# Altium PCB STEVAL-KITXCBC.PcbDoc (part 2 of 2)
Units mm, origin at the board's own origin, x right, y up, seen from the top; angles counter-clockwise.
Board outline 110 x 100 mm, 4 copper layers (Top Layer, Ground Layer, Power Layer, Bottom Layer), stack 1.572 mm thick; 141 components, 96 nets, 501 pads, 315 vias.
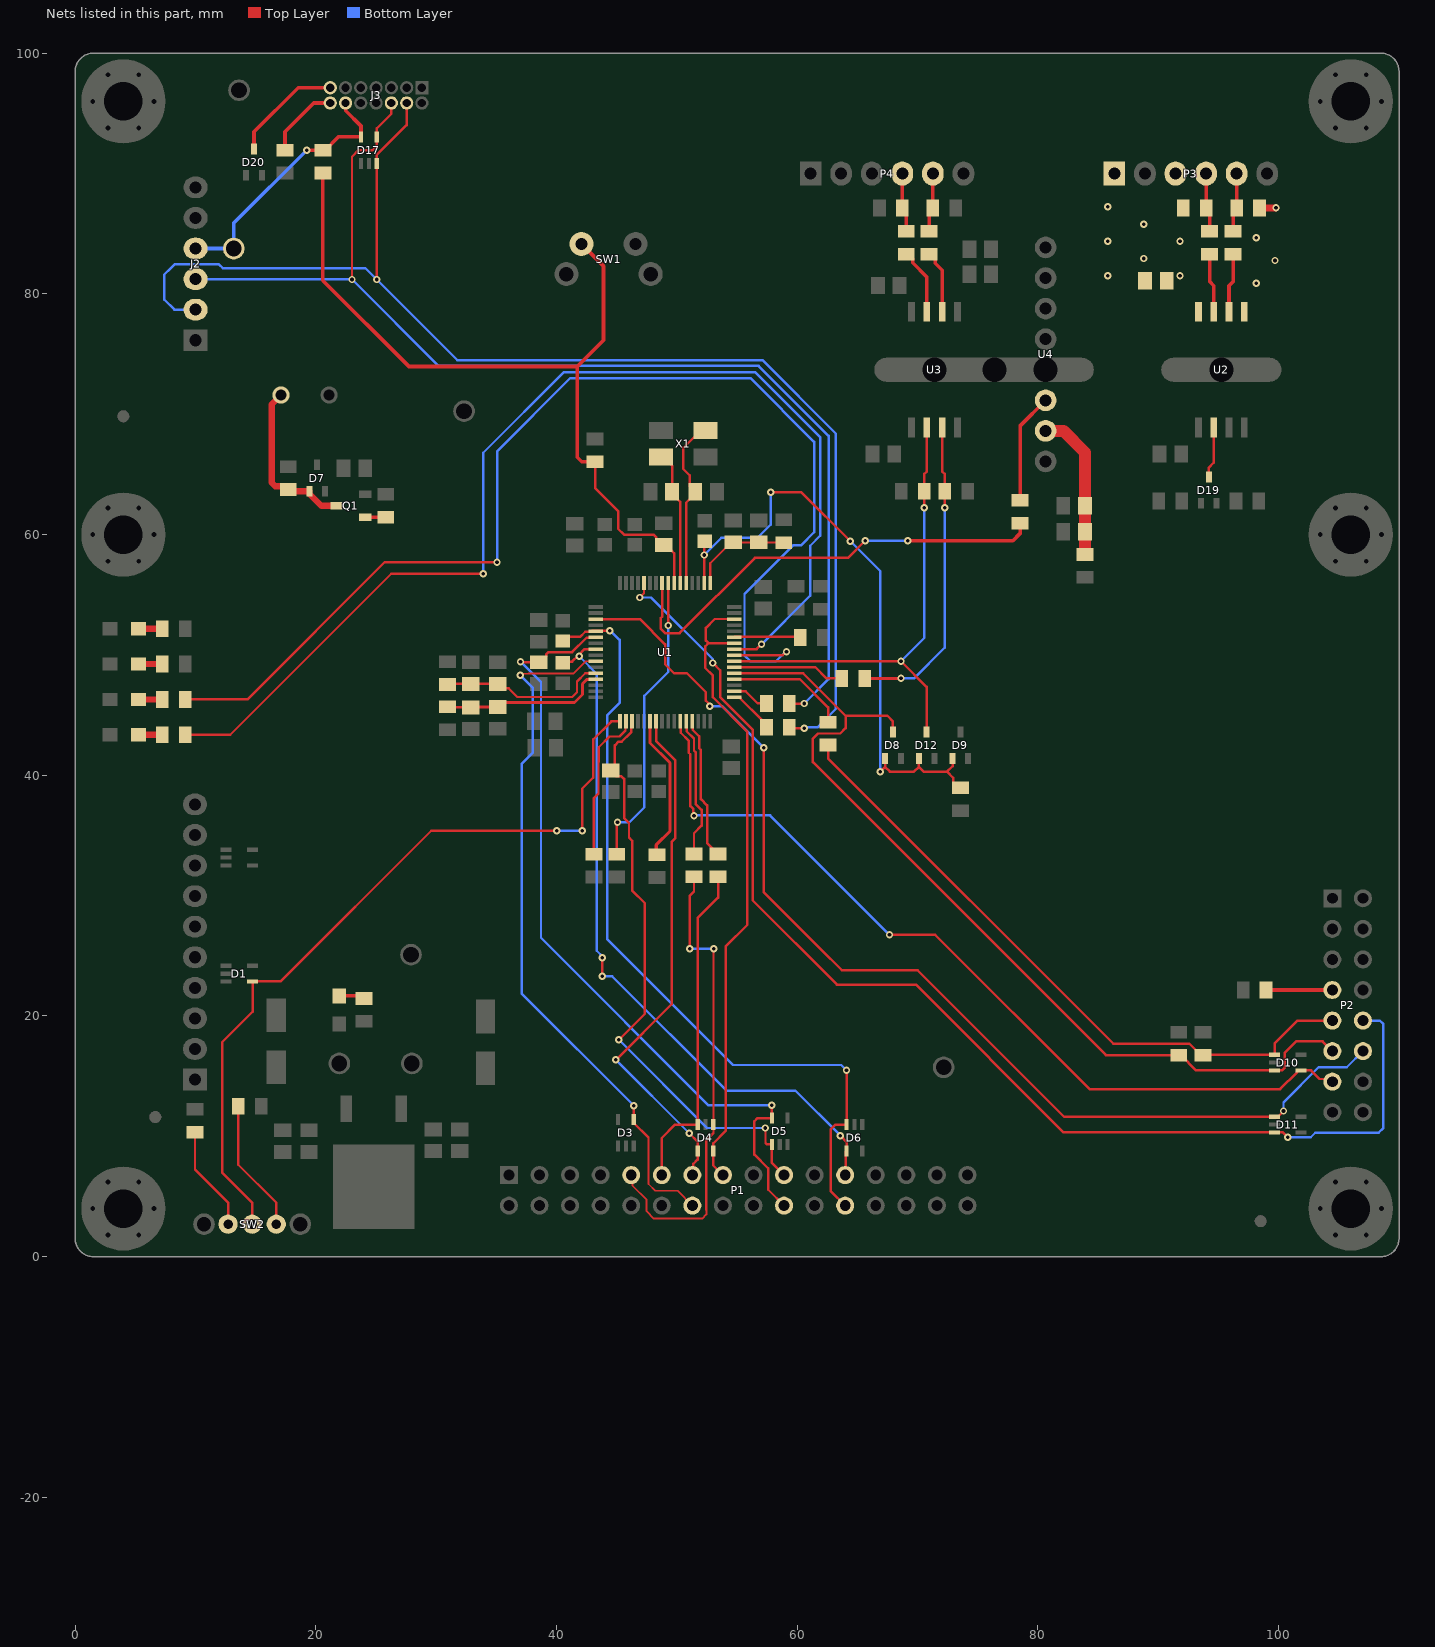
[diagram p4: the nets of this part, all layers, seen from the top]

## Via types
v1: diameter 0.61, hole 0.305, Top Layer to Bottom Layer, tented both sides, 249 vias
v2: diameter 0.6, hole 0.3, Top Layer to Bottom Layer, tented both sides, 45 vias
v3: diameter 0.65, hole 0.3, Top Layer to Bottom Layer, 12 vias
v4: diameter 0.62, hole 0.31, Top Layer to Bottom Layer, 9 vias

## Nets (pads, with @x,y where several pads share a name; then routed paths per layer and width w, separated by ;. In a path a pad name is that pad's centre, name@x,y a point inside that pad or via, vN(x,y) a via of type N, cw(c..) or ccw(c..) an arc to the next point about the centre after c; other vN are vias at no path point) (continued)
Led2: R36.2 U1.56 | length 100
  Top Layer w0.203: R36.2@9.009,46.306 14.319,46.306 25.713,57.7 v1(35.05,57.7) ; U1.56@54.764,49.979 58.786,49.979 59.061,50.254 v1(59.109,50.254)
  Bottom Layer w0.203: v1(35.05,57.7) 35.05,66.916 41.134,73 56.1,73 61.4,67.7 61.4,60.2 60.3,59.1 59.652,59.1 55.615,55.063 55.615,49.967 56.103,49.479 58.228,49.479 59.003,50.254 v1(59.109,50.254)
Led3: R37.2 U1.57 | length 95.2
  Top Layer w0.203: R37.2@9.009,43.369 12.884,43.369 26.264,56.75 v1(33.9,56.75) ; U1.57@54.764,50.479 56.623,50.479 v1(57.026,50.882)
  Bottom Layer w0.203: v1(33.9,56.75) 33.9,66.8 40.6,73.5 56.5,73.5 61.9,68.1 61.9,59.9 61.072,59.072 61.072,54.928 v1(57.026,50.882)
LINEen: D3.4 P1.14 U1.26 | length 58.8
  Top Layer w0.152: v4(36.969,48.307) 37.106,48.444 37.663,48.444 37.688,48.469 41.429,48.469 42.439,49.479 U1.26@43.264,49.479 ; 47.636,8.339 47.636,6.036 48.2,5.472 50.048,5.472 P1.14@51.28,4.24
  Top Layer w0.203: v1(46.406,12.548) 46.406,11.121 47.636,9.891 47.636,8.339
  Bottom Layer w0.203: v4(36.969,48.307) v4@37.117,48.16 ; v4@37.117,48.307 v4@37.117,48.16 ; v1(46.406,12.548) 37.117,21.837 37.117,40.976 38.031,41.891 38.031,47.246 v4@37.117,48.16
NetBZ1_2: BZ1.2 D7.1 Q1.3 R16.1 | length 13.8
  Top Layer w0.508: BZ1.2@17.1,71.6 16.327,70.827 16.327,64.319 16.625,64.021 17.429,64.021 R16.1@17.7,63.75 ; R16.1@17.775,63.75 17.95,63.75 18.1,63.6 D7.1@19.45,63.6 19.45,63.408 20.458,62.4 Q1.3@21.7,62.4
NetC22_1: C22.1 C23.1 R28.2 U1.29 | length 13.8
  Top Layer w0.203: R28.2@30.933,45.697 30.968,45.662 C22.1@32.857,45.662
  Top Layer w0.254: C22.1@32.857,45.647 32.872,45.662 C23.1@35.107,45.662 35.32,45.662 35.705,46.047 41.49,46.047 42.151,46.708 42.151,47.604 42.505,47.958 43.243,47.958 U1.29@43.264,47.979
NetC25_1: C25.1 C26.1 R29.2 U1.1 | length 8.5
  Top Layer w0.203: U1.1@52.764,55.979 52.764,57.619 54.094,58.948 54.244,58.948 C26.1@54.666,59.371 54.691,59.346 56.808,59.346 58.853,59.346 R29.2@58.878,59.321
NetC28_1: C28.1 C29.1 R39.2 U1.28 | length 14.1
  Top Layer w0.203: R39.2@30.933,47.55 30.983,47.6 C28.1@32.857,47.6 C29.1@35.107,47.6 35.489,47.218 35.639,47.218 36.018,47.218 36.732,46.505 41.301,46.505 41.693,46.897 41.693,47.793 42.38,48.479 U1.28@43.264,48.479
NetC30_1: C30.1 C31.1 R41.1 U4.2 | length 12.5
  Top Layer w1: U4.2@80.642,68.62 82.118,68.62 83.9,66.838 C31.1@83.9,62.384 C30.1@83.9,60.234 R41.1@83.9,58.35
NetD18_1: D18.1 R45.1 | length 2.1
  Top Layer w0.3: D18.1@21.948,21.675 23.775,21.675 R45.1@24,21.45
NetD19_3: D19.3 U2.2 | length 4.3
  Top Layer w0.203: D19.3@94.2,64.8 94.2,65.573 94.605,65.978 U2.2@94.605,68.899
NetD20_3: D20.3 J3.13 | length 9.3
  Top Layer w0.3: D20.3@14.854,92.056 14.854,93.464 18.525,97.135 J3.13@21.19,97.135
NetJ3_14: J3.14 R44.1 | length 6.3
  Top Layer w0.3: R44.1@17.43,91.95 17.43,93.486 19.809,95.865 J3.14@21.19,95.865
NetLED0_1: LED0.1 R34.1 | length 2
  Top Layer w0.508: LED0.1@5.244,52.178 R34.1@7.236,52.178
NetLED1_1: LED1.1 R35.1 | length 1.9
  Top Layer w0.508: LED1.1@5.244,49.242 R35.1@7.109,49.242
NetLED2_1: LED2.1 R36.1 | length 1.9
  Top Layer w0.508: LED2.1@5.244,46.305 R36.1@7.109,46.305
NetLED3_1: LED3.1 R37.1 | length 1.9
  Top Layer w0.508: LED3.1@5.244,43.369 R37.1@7.109,43.369
NetP2_7: P2.7 R13.2 | length 5.5
  Top Layer w0.3: R13.2@98.95,22.16 P2.7@104.46,22.16
NetP3_4: P3.4 R23.1 R26.2 | length 4.9
  Top Layer w0.3: P3.4@93.97,90 R23.1@93.97,87.147 94.266,86.851 R26.2@94.266,85.204
NetP3_5: P3.5 R24.1 R27.2 | length 4.9
  Top Layer w0.3: R27.2@96.214,85.204 96.214,86.851 R24.1@96.51,87.147 P3.5@96.51,90
NetP4_4: P4.4 R32.1 R38.2 | length 4.9
  Top Layer w0.3: P4.4@68.73,90 R32.1@68.73,87.15 69.05,86.83 R38.2@69.05,85.2
NetP4_5: P4.5 R33.1 R40.2 | length 4.9
  Top Layer w0.3: R40.2@70.95,85.2 70.95,86.83 R33.1@71.27,87.15 P4.5@71.27,90
NetQ1_1: Q1.1 R20.1 | length 1.7
  Top Layer w0.3: Q1.1@24.1,61.45 R20.1@25.8,61.45
NetR3_1: R3.1 U1.8 | length 24.9
  Top Layer w0.203: R3.1@45,33.45 45,36.038 v1(45.06,36.097) ; U1.8@49.264,55.979 49.264,52.466 v1(49.279,52.451)
  Bottom Layer w0.203: v1(45.06,36.097) 46.046,36.097 47.298,37.349 47.298,46.608 49.279,48.589 v1(49.279,52.451)
NetR4_1: R4.1 U1.38 | length 12.3
  Top Layer w0.254: U1.38@47.764,44.479 47.764,42.689 49.42,41.033 49.42,35.359 48.28,34.219 48.28,33.469 R4.1@48.342,33.407
NetR5_1: R5.1 U1.44 | length 11.8
  Top Layer w0.203: U1.44@50.764,44.479 50.815,44.428 50.815,43.867 50.817,43.865 50.817,43.65 51.416,43.05 51.416,42.054 51.554,41.916 51.554,37.625 52.051,37.127 52.051,35.821 51.416,35.186 R5.1@51.416,33.457
NetR6_1: R6.1 U1.52 | length 10
  Top Layer w0.203: U1.52@54.764,47.979 60.216,47.979 62.557,45.638 R6.1@62.557,44.422
NetR7_1: R7.1 U1.45 | length 11.9
  Top Layer w0.203: U1.45@51.264,44.479 51.315,44.428 51.315,43.762 51.848,43.229 51.848,42.232 51.985,42.095 51.985,38.015 52.5,37.5 52.5,34.379 R7.1@53.421,33.457
NetR8_2: R8.2 U1.49 | length 3.9
  Top Layer w0.203: U1.49@54.764,46.479 55.209,46.479 55.259,46.428 55.259,46.391 57.021,44.63 57.021,44.332 R8.2@57.444,43.909
NetR9_1: R9.1 U1.54 | length 9.3
  Top Layer w0.203: U1.54@54.764,48.979 61.504,48.979 62.426,48.057 R9.1@63.703,48.057
NetR10_2: R10.2 U1.50 | length 3.1
  Top Layer w0.203: U1.50@54.764,46.979 55.708,46.979 56.712,45.974 R10.2@57.444,45.974
NetR15_2: R15.2 U1.59 | length 5.5
  Top Layer w0.203: U1.59@54.764,51.479 54.802,51.517 60.219,51.517 R15.2@60.256,51.479
NetR19_1: R19.1 U1.34 | length 12.6
  Top Layer w0.203: R19.1@43.1,33.45 43.1,38.1 43.48,38.48 43.48,41.097 43.5,41.117 43.5,42.334 44.391,43.225 45.233,43.225 45.726,43.718 45.726,44.441 U1.34@45.764,44.479
NetR25_1: R25.1 SW2.3 | length 11.1
  Top Layer w0.203: R25.1@13.55,12.5 13.55,7.639 16.7,4.489 SW2.3@16.7,2.7
NetR26_1: R26.1 U2.7 | length 4.9
  Top Layer w0.3: R26.1@94.266,83.304 94.266,81.028 94.605,80.689 U2.7@94.605,78.508
NetR27_1: R27.1 U2.6 | length 4.9
  Top Layer w0.3: U2.6@95.875,78.508 95.875,80.689 96.214,81.028 R27.1@96.214,83.304
NetR38_1: R38.1 U3.7 | length 5.6
  Top Layer w0.3: R38.1@69.05,83.3 69.218,83.3 69.593,82.925 69.593,82.582 70.765,81.41 U3.7@70.765,78.501
NetR40_1: R40.1 U3.6 | length 5.3
  Top Layer w0.3: R40.1@70.95,83.3 71.081,83.3 71.456,82.925 71.456,82.544 72.035,81.965 U3.6@72.035,78.501
NetR43_1: R43.1 SW2.1 | length 8.8
  Top Layer w0.203: R43.1@9.95,10.337 9.95,7.239 11.941,5.248 12.7,4.489 SW2.1@12.7,2.7
NFC_Reset: D11.3 P2.10 U1.12 | length 102.3
  Top Layer w0.203: v1(46.916,54.775) 47.264,55.122 U1.12@47.264,55.979 ; v1(52.984,49.327) 53.587,48.724 53.587,46.49 56.286,43.791 56.286,29.614 63.296,22.604 69.851,22.604 82.132,10.323 D11.3@99.662,10.323 100.362,10.323 v1(100.762,9.923)
  Bottom Layer w0.203: v1(46.916,54.775) 47.853,54.775 52.984,49.644 v1(52.984,49.327) ; v1(100.762,9.923) 102.662,9.923 103.04,10.3 108.3,10.3 108.7,10.7 108.7,19.32 108.4,19.62 P2.10@107,19.62
NFC_spare: D10.4 P2.13 U1.43 | length 71.8
  Top Layer w0.203: U1.43@50.264,44.479 50.315,44.428 50.315,43.867 50.317,43.865 50.317,43.539 50.966,42.89 50.966,41.894 50.985,41.875 51.122,41.737 51.122,37.446 51.339,37.229 51.339,36.728 v1(51.416,36.65) ; v1(67.661,26.739) 71.461,26.739 84.281,13.919 100.117,13.919 101.513,15.316 101.513,15.331 101.662,15.479 102.69,15.479 103.405,14.764 104.236,14.764 P2.13@104.46,14.54
  Bottom Layer w0.203: v1(51.416,36.65) 51.432,36.666 57.734,36.666 v1(67.661,26.739)
NFC_Uart_Rx: D8.3 D10.3 P2.11 R11.1 U1.53 | length 77.6
  Top Layer w0.203: U1.53@54.764,48.479 60.481,48.479 64.013,44.947 ; D8.3@67.95,43.6 67.95,44.481 67.484,44.947 64.013,44.947 ; P2.11@104.46,17.08 103.653,17.887 101.447,17.887 100.512,16.952 100.512,15.729 100.262,15.479 D10.3@99.662,15.479 93.146,15.479 91.875,16.75 R11.1@91.7,16.75 85.65,16.75 61.3,41.1 61.3,43.047 61.725,43.472 63.565,43.472 64.013,43.92 64.013,44.947
NFC_Uart_Tx: D10.1 P2.9 R6.2 R12.1 | length 55
  Top Layer w0.203: R6.2@62.557,42.522 62.557,41.401 86.259,17.7 92.575,17.7 93.525,16.75 R12.1@93.7,16.75 93.729,16.779 D10.1@99.662,16.779 99.662,17.702 101.58,19.62 P2.9@104.46,19.62
NFC_Wake_Up: D11.1 P2.12 U1.19 | length 92
  Top Layer w0.203: U1.19@43.264,52.979 46.917,52.979 49.016,50.88 49.016,49.227 49.764,48.479 50.824,48.479 52.399,46.905 52.399,46.195 52.739,45.855 v1(52.739,45.745) ; v1(57.2,42.3) 57.2,30.302 61.902,25.6 63.702,23.8 70,23.8 82.177,11.623 D11.1@99.662,11.623 99.937,11.623 100.4,12.086 v1(100.4,12.1)
  Bottom Layer w0.203: v1(52.739,45.745) 53.755,45.745 v1(57.2,42.3) ; v1(100.4,12.1) 100.4,12.821 103.318,15.739 105.659,15.739 P2.12@107,17.08
NRST: C1.1 R1.2 R2.1 SW1.3 U1.7 | length 68
  Top Layer w0.203: R1.2@43.2,66.05 43.2,63.859 45.112,61.948 45.112,60.488 45.6,60 48.062,60 48.293,59.769 48.293,59.619 48.766,59.146 C1.1@48.916,59.146 C1.1@49.066,59.146 ; C1.1@49.54,58.672 49.764,58.448 U1.7@49.764,55.979
  Top Layer w0.3: R2.1@20.579,90.237 20.579,81.123 27.734,73.968 41.709,73.968 ; SW1.3@42.065,84.15 43.9,82.315 43.9,76.16 41.709,73.968 ; R1.2@43.2,66.05 42.081,66.05 41.709,66.423 41.709,73.968
OSC1_1: C3.1 U1.5 X1.3 | length 14.4
  Top Layer w0.203: U1.5@50.764,55.979 50.764,57.627 50.764,62.643 51.525,63.404 C3.1@51.525,63.554 51.052,64.028 51.052,64.933 50.525,65.46 50.525,67.21 51.975,68.66 X1.3@52.375,68.66
OSC1_2: C2.2 U1.6 X1.1 | length 11.3
  Top Layer w0.203: X1.1@48.675,66.46 48.875,66.46 49.594,65.741 C2.2@49.594,63.554 49.594,63.404 50.264,62.734 U1.6@50.264,55.979
PWM_1H: D4.1 P1.9 R5.2 | length 39.4
  Top Layer w0.152: P1.9@46.2,6.78 46.306,6.674 46.306,5.891 47.473,4.724 47.473,3.774 48.079,3.167 52.105,3.167 52.449,3.511 52.449,3.881
  Top Layer w0.203: v1(51.05,25.6) 51.05,29.972 51.416,30.338 R5.2@51.416,31.557 ; 52.449,3.881 52.449,9.675 53.038,10.265 53.038,10.97 53.035,10.974 53.036,25.586 v1(53.05,25.6)
  Bottom Layer w0.203: v1(51.05,25.6) v1(53.05,25.6)
PWM_1L*: D4.3 P1.11 R7.2 | length 27.6
  Top Layer w0.203: P1.11@48.74,6.78 48.74,9.861 49.85,10.97 D4.3@51.721,10.97 ; D4.3@51.721,11.215 51.721,28.136 53.421,29.836 R7.2@53.421,31.557
PWM_en/SD*: D4.4 P1.13 U1.39 | length 43.5
  Top Layer w0.203: v1(44.923,16.351) 49.551,20.98 49.551,34.455 49.877,34.781 49.877,41.222 48.264,42.835 U1.39@48.264,44.479 ; v1(51.021,10.252) 51.714,9.559 51.714,9.022 D4.4@51.721,9.015 ; P1.13@51.28,6.78 51.367,6.866 51.367,7.716 51.721,8.07 D4.4@51.721,8.77
  Bottom Layer w0.203: v1(44.923,16.351) v1(51.021,10.252) ; P1.13@51.28,6.78 P1.13@51.512,7.012
Remote: R42.1 U4.3 | length 9.2
  Top Layer w0.3: R42.1@78.512,62.857 78.512,69.03 U4.3@80.642,71.16
ResetDSP: D17.5 J2.4 J3.12 R2.2 TP1.1 | length 22.2
  Top Layer w0.3: v1(19.229,91.95) R2.2@20.6,91.95 20.775,91.95 21.875,93.05 D17.5@23.75,93.05 ; J3.12@22.484,96.06 22.484,95.216 23.75,93.95 D17.5@23.75,93.25
  Bottom Layer w0.3: J2.4@10,83.77 TP1.1@13.17,83.77 13.17,85.891 v1(19.229,91.95)
Selector: D1.4 SW2.2 U1.33 | length 65.6
  Top Layer w0.203: SW2.2@14.7,2.7 14.7,4.489 12.2,6.989 12.2,17.817 14.733,20.35 D1.4@14.733,22.868 17.065,22.868 29.586,35.389 v1(40.002,35.389) ; v1(42.13,35.389) 42.13,38.889 43.049,39.807 43.049,42.978 44.55,44.479 U1.33@45.264,44.479
  Bottom Layer w0.203: v1(40.002,35.389) v1(42.13,35.389)
Supply_EN: R42.2 U1.9 | length 38.2
  Top Layer w0.203: U1.9@48.764,55.979 48.764,53.179 48.644,53.059 48.644,52.188 49.016,51.816 50.227,51.816 56.475,58.064 64.213,58.064 v1(65.642,59.493)
  Top Layer w0.3: v1(69.175,59.493) 77.92,59.493 78.512,60.085 R42.2@78.512,60.957
  Bottom Layer w0.203: v1(65.642,59.493) v1(69.175,59.493)
SWCLK: D17.4 J2.3 J3.6 R10.1 | length 99
  Top Layer w0.203: v1(23,81.2) 23,91.397 23.553,91.95 24.737,91.95 25.05,92.263 D17.4@25.05,93.05 25.05,93.75 26.27,94.97 J3.6@26.27,95.865 ; R10.1@59.344,45.926 60.53,45.926 v1(60.573,45.97)
  Bottom Layer w0.203: J2.3@10,81.23 10.015,81.215 22.985,81.215 30.184,74.016 56.784,74.016 62.6,68.2 62.6,47.997 v1(60.573,45.97)
SWDIO: D17.3 J2.2 J3.4 R8.1 | length 110.1
  Top Layer w0.203: v1(25.042,81.2) 25.046,81.204 25.046,90.846 25.042,90.85 25.042,91.531 27.54,94.029 J3.4@27.54,95.865 ; R8.1@59.344,43.909 v1(60.573,43.909)
  Bottom Layer w0.203: J2.2@10,78.69 8.234,78.69 7.4,79.524 7.4,81.6 7.944,82.144 8.26,82.46 11.938,82.46 12.255,82.144 24.098,82.144 31.742,74.5 57.1,74.5 63.2,68.4 63.2,45.515 61.672,43.987 60.651,43.987 v1(60.573,43.909)
TempSens2: C14.1 D5.1 P1.19 U1.35 | length 49.8
  Top Layer w0.152: P1.19@58.9,6.78 P1.19@59.013,6.667
  Top Layer w0.203: v1(45.173,18.021) 47.335,20.182 47.335,29.363 46.273,30.425 46.273,34.565 46.017,34.822 46.017,36.038 45.605,36.45 45.605,39.695 45.362,39.938 44.962,39.938 C14.1@44.5,40.4 44.843,40.743 44.843,42.487 45.15,42.793 45.412,42.793 46.097,43.479 46.097,43.481 46.213,43.597 46.213,44.428 U1.35@46.264,44.479 ; v1(57.336,10.693) 57.357,10.671 57.357,9.448 57.477,9.329 D5.1@57.879,9.329 ; D5.1@57.892,9.316 57.892,7.789 P1.19@58.9,6.78
  Bottom Layer w0.203: v1(45.173,18.021) 52.501,10.693 v1(57.336,10.693)
TempSens3: C10.1 D5.5 P1.20 U1.22 | length 66.5
  Top Layer w0.203: v4(36.999,49.445) 37.045,49.4 C10.1@38.5,49.4 38.65,49.4 39.123,49.873 39.123,50.023 39.33,50.23 41.295,50.23 42.493,51.428 43.213,51.428 U1.22@43.264,51.479 ; v1(57.887,12.573) 57.882,12.568 57.882,11.527 D5.5@57.892,11.516 56.7,11.516 56.436,11.253 56.436,8.486 57.582,7.341 57.582,5.558 P1.20@58.9,4.24
  Bottom Layer w0.203: v4(36.999,49.445) 38.702,47.742 38.702,26.498 52.627,12.573 v1(57.887,12.573)
Ubridge: C11.1 D6.3 P1.24 U1.21 | length 68.6
  Top Layer w0.203: C11.1@40.5,51.15 40.85,51.5 41.954,51.5 42.382,51.928 U1.21@42.905,51.928 ; U1.21@43.485,51.985 43.428,51.928 U1.21@42.905,51.928 ; v4(44.424,52) 42.977,52 U1.21@42.905,51.928 ; P1.24@63.98,4.24 62.763,5.457 62.763,10.568 63.165,10.97 D6.3@64.092,10.97 v1(64.092,15.5)
  Bottom Layer w0.203: v4(44.424,52) 44.484,52 45.231,51.253 45.231,46.015 44.2,44.984 44.2,26.381 54.656,15.926 63.656,15.926 64.082,15.5 v1(64.092,15.5)
UDC: C16.1 D6.4 P1.23 U1.24 | length 59.7
  Top Layer w0.203: C16.1@40.5,49.35 40.595,49.445 41.286,49.445 v3@41.803,49.962 ; v3(41.878,49.887) v3@41.803,49.962 ; U1.24@43.264,50.479 42.32,50.479 v3@41.803,49.962 ; v1(43.8,23.3) v1(43.8,24.85) ; v1(63.576,10.058) 64.092,9.542 D6.4@64.092,8.77 64.036,8.714 64.036,6.836 P1.23@63.98,6.78 P1.23@63.98,6.972
  Bottom Layer w0.203: v3(41.878,49.887) 43.336,48.429 43.336,25.417 43.8,24.953 v1(43.8,24.85) ; v1(43.8,23.3) 44.608,23.3 54.108,13.8 59.835,13.8 v1(63.576,10.058)
UI_Rx: D12.3 R31.1 U1.55 U3.2 | length 40.9
  Top Layer w0.203: U1.55@54.764,49.479 v1(68.621,49.479) 70.75,47.35 D12.3@70.75,43.6 ; v1(70.55,62.229) R31.1@70.55,63.6 70.55,65.041 70.765,65.256 U3.2@70.765,68.899
  Bottom Layer w0.203: v1(68.621,49.479) 70.55,51.408 v1(70.55,62.229)
UI_Tx: R9.2 R30.1 U3.3 | length 26.1
  Top Layer w0.203: U3.3@72.035,68.899 72.035,65.256 72.25,65.041 R30.1@72.25,63.6 v1(72.25,62.229)
  Top Layer w0.254: R9.2@65.603,48.057 v1(68.621,48.057)
  Bottom Layer w0.203: v1(68.621,48.057) 69.702,48.057 72.25,50.605 v1(72.25,62.229)
"VDD iso": C20.1 P3.3 R23.2 R24.2 U2.8 | length 1.4
  Top Layer w0.6: R24.2@98.41,87.147 v1(99.781,87.147)
  other v1: 91.8,81.506 91.8,84.369
"VSS iso": C20.2 P3.1 U2.5
  other v1: 98.136,80.879 85.8,81.506 99.698,82.779 88.8,82.937 85.8,84.369 98.136,84.679 88.8,85.8 85.8,87.231
"Wake up": C5.1 D8.1 D9.1 D12.1 R14.1 U1.2 | length 52
  Top Layer w0.203: U1.2@52.264,55.979 v2(52.264,58.309) 52.264,59.414 C5.1@52.3,59.45 ; v1(57.791,63.508) 60.352,63.508 v1(64.402,59.458) ; v1(66.9,40.3) 67.3,40.7 ; D8.1@67.3,41.4 67.3,40.7 ; D12.1@70.1,41.4 70.1,40.7 ; D9.1@72.9,41.4 72.9,40.75 72.45,40.3 ; R14.1@73.55,38.95 73.375,38.95 72.952,39.373 72.952,39.798 72.45,40.3 ; 67.3,40.7 67.7,40.3 69.7,40.3 70.1,40.7 ; 70.1,40.7 70.5,40.3 72.45,40.3
  Bottom Layer w0.203: v2(52.264,58.309) 53.693,59.738 56.695,59.738 57.791,60.834 v1(57.791,63.508) ; v1(64.402,59.458) 66.9,56.96 v1(66.9,40.3)
Zero-X: D4.5 P1.15 U1.58 U1.62 | length 53.4
  Top Layer w0.203: P1.15@53.82,6.78 53.021,7.579 D4.5@53.021,8.77 53.021,9.415 54.047,10.441 54.047,25.778 55.855,27.586 55.855,43.612 52.984,46.482 52.984,48.282 52.349,48.917 52.349,50.717 52.612,50.979 ; U1.58@54.764,50.979 52.612,50.979 ; U1.62@54.764,52.979 54.754,52.989 53.142,52.989 52.4,52.248 52.4,51.191 52.612,50.979
pads on no net: D2.5 D3.5 D5.3 D7.2 D8.2 D9.2 D12.2 D17.1 D19.2 D20.2 FID1.1 FID2.1 FID3.1 FID4.1 FID5.1 FID6.1 H1.1 H2.1 H3.1 H4.1 H5.1 H6.1 J1.2 J2.6 J3.1 J3.2 J3.8 J3.9 J3.10 P1.22 P3.2 P3.6 P4.2 P4.6 SW1.1 SW1.4 SW2. U1.4 U4. U4.5 U4.8

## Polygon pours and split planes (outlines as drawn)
GND on Top Layer "TOP_LAYER_GND_P171" (solid, remove dead copper, pour order 171): 109.6,99.482 109.6,2.411 107.589,0.4 1.5,0.4 0.4,1.5 0.4,98.266 1.615,99.482
+3V3 on Top Layer "TOP_LAYER_+3V3_P170" (solid, remove dead copper, pour order 170): 45.416,56.967 44.993,57.39 44.04,57.39 43.637,57.793 43.637,59.64 43.409,59.868 41.517,59.868 41.495,59.846 41.495,56.694 42.806,55.382 45.416,55.382
+3V3 on Top Layer "TOP_LAYER_+3V3_P169" (solid, remove dead copper, pour order 169): 52.612,45.076 53.857,45.076 55.363,43.57 55.363,38.911 55.202,38.75 53.972,38.75 53.865,38.858 53.865,42.975 53.211,43.628 52.866,43.628 52.612,43.882
+3V3 on Top Layer "TOP_LAYER_+3V3_P168" (solid, remove dead copper, pour order 168): 43.861,44.022 43.861,46.632 42.667,46.632 42.413,46.378 42.413,45.815 41.45,44.852 39.603,44.852 39.375,44.624 39.375,39.44 39.571,39.245 42.456,39.245 43.141,39.93 43.141,43.302
+5V on Top Layer "TOP_LAYER_+5V_P150" (solid, remove dead copper, pour order 150): 32.45,10.35 33.2,9.6 33.2,2.635 35.092,0.743 41.593,0.743 42.314,1.464 42.314,12.054 36.814,17.554 26.909,17.554 25.83,16.475 25.83,10.924 26.404,10.35
+3V3 on Top Layer "TOP_LAYER_+3V3_P149" (solid, remove dead copper, pour order 149): 15.169,17.113 15.602,17.546 22.81,17.546 23.571,16.785 23.571,10.875 22.997,10.3 16.033,10.3 15.169,11.164
"GND iso" on Top Layer "TOP_LAYER_NONET_P-001" (solid, remove dead copper, pour order 177): 61.374,84.04 58.06,87.354 58.06,93.284 58.84,94.064 80.336,94.064 82.4,92 82.4,78.1 81.988,77.688 67.726,77.688
+5V on Top Layer "TOP_LAYER_+5V_P163" (solid, remove dead copper, pour order 163): 82.276,57.061 81.918,56.703 81.918,54.826 82.276,54.468 85.524,54.468 85.882,54.826 85.882,56.703 85.524,57.061
"VSS iso" on Top Layer "TOP_LAYER_VSS_ISO_P173" (solid, remove dead copper, pour order 173): 91.595,77.696 90.083,79.208 86.837,79.208 84.9,81.145 84.9,93.884 85.08,94.064 100.32,94.064 100.5,93.884 100.5,79.3 98.896,77.696
"VDD iso" on Top Layer "TOP_LAYER_VDD_ISO_P154" (solid, remove dead copper, pour order 154): 90.453,91.498 90.083,91.128 90.083,79.208 91.595,77.696 94.266,77.696 94.266,89.691 92.459,91.498
+3V3 on Top Layer "TOP_LAYER_+3V3_P167" (solid, remove dead copper, pour order 167): 54.167,53.827 54.167,55.168 56.312,57.313 60.709,57.313 60.85,57.171 60.85,55.13 60.8,55.08 56.269,55.08 56.05,54.861 56.05,54.099 55.778,53.827
+5V on Top Layer "TOP_LAYER_+5V_P166" (solid, remove dead copper, pour order 166): 95.735,9.16 95.481,8.906 95.481,7.432 95.735,7.178 97.208,7.178 97.488,7.458 97.488,8.88 97.208,9.16
+5V on Top Layer "TOP_LAYER_+5V_P165" (solid, remove dead copper, pour order 165): 95.735,9.16 95.481,8.906 95.481,7.432 95.735,7.178 97.208,7.178 97.488,7.458 97.488,8.88 97.208,9.16
+24V on Top Layer "TOP_LAYER_+24V_P162" (solid, remove dead copper, pour order 162): 88.09,21.542 87.836,21.288 87.836,19.815 88.09,19.561 89.563,19.561 89.842,19.84 89.842,21.262 89.563,21.542
+24V on Top Layer "TOP_LAYER_+24V_P153" (solid, remove dead copper, pour order 153): 88.09,21.542 87.836,21.288 87.836,19.815 88.09,19.561 89.563,19.561 89.842,19.84 89.842,21.262 89.563,21.542
no net on Top Overlay "TOP_LAYER_NONET_P-001" (hatched 45Degree grid 0.75 track 0.2): 50.06,84.04 50.06,100 58.06,100 58.06,87.354 61.374,84.04 67.726,77.688 110,77.688 110,69.712 64.388,69.712 57.3,76.8
GND on Bottom Layer "BOTTOM_LAYER_GND_P164" (solid, remove dead copper, pour order 164): 109.257,99.482 109.257,2.068 107.589,0.4 1.5,0.4 0.706,1.194 0.706,98.572 1.615,99.482 74.519,99.482
+3V3 on Bottom Layer "BOTTOM_LAYER_+3V3_P152" (solid, remove dead copper, pour order 152): 15.948,17.053 16.441,17.546 22.81,17.546 23.571,16.785 23.571,10.384 23.119,9.931 16.402,9.931 15.948,10.385
+5V on Bottom Layer "BOTTOM_LAYER_+5V_P151" (solid, remove dead copper, pour order 151): 25.83,10.924 26.708,10.046 34.848,10.046 35.627,10.824 35.627,17.117 35.19,17.554 26.909,17.554 25.83,16.475
"GND iso" on Bottom Layer "TOP_LAYER_NONET_P-001" (solid, pour order 161): 61.374,84.04 58.06,87.354 58.06,93.284 58.84,94.064 80.336,94.064 82.4,92 82.4,78.1 81.988,77.688 67.726,77.688
+5V on Bottom Layer "BOTTOM_LAYER_+5V_P159" (solid, remove dead copper, pour order 159): 82.276,57.061 81.918,56.703 81.918,54.826 82.276,54.468 85.524,54.468 85.882,54.826 85.882,56.703 85.524,57.061
"VSS iso" on Bottom Layer "BOTTOM_LAYER_VSS_ISO_P160" (solid, remove dead copper, pour order 160): 91.595,77.696 90.083,79.208 86.837,79.208 84.9,81.145 84.9,93.884 85.08,94.064 100.32,94.064 100.5,93.884 100.5,79.3 98.896,77.696
+5V on Bottom Layer "BOTTOM_LAYER_+5V_P158" (solid, remove dead copper, pour order 158): 95.735,9.16 95.481,8.906 95.481,7.432 95.735,7.178 97.208,7.178 97.488,7.458 97.488,8.88 97.208,9.16
+24V on Bottom Layer "BOTTOM_LAYER_+24V_P157" (solid, remove dead copper, pour order 157): 88.09,21.542 87.836,21.288 87.836,19.815 88.09,19.561 89.563,19.561 89.842,19.84 89.842,21.262 89.563,21.542
GND on Ground Layer "GROUND_LAYER_GND_P156" (solid, remove dead copper, pour order 156): 109.6,99.482 109.6,2.411 107.589,0.4 1.5,0.4 0.4,1.5 0.4,98.266 1.615,99.482
"GND iso" on Ground Layer "TOP_LAYER_NONET_P-001" (solid, pour order 175): 61.374,84.04 58.06,87.354 58.06,93.284 58.84,94.064 80.336,94.064 82.4,92 82.4,78.1 81.988,77.688 67.726,77.688
"VSS iso" on Ground Layer "GROUND_LAYER_VSS_ISO_P172" (solid, remove dead copper, pour order 172): 91.595,77.696 90.083,79.208 86.837,79.208 84.9,81.145 84.9,93.884 85.08,94.064 100.32,94.064 100.5,93.884 100.5,79.3 98.896,77.696
Gnd1 on Ground Layer "GROUND_LAYER_GND1_P155" (solid, remove dead copper, pour order 155): 50.428,55.365 50.121,55.365 50.063,55.423 50.063,62.205 49.714,62.554 47.029,62.554 46.817,62.767 46.817,64.054 45.811,65.06 45.811,69.141 46.73,70.06 53.84,70.06 54.647,69.253 54.647,65.16 54.048,64.561 54.048,62.693 53.909,62.554 51.277,62.554 50.95,62.228 50.95,55.4 50.915,55.365
+3V3 on Power Layer "POWER_LAYER_+3V3_P148" (solid, remove dead copper, pour order 148): 109.257,99.482 74.524,99.482 1.615,99.482 0.4,98.266 0.4,1.5 1.5,0.4 107.589,0.4 109.257,2.068
"+5V iso" on Power Layer "TOP_LAYER_NONET_P-001" (solid, pour order 176): 61.374,84.04 58.06,87.354 58.06,93.284 58.84,94.064 80.336,94.064 82.4,92 82.4,78.1 81.988,77.688 67.726,77.688
"VDD iso" on Power Layer "POWER_LAYER_VDD_ISO_P174" (solid, remove dead copper, pour order 174): 91.595,77.696 90.083,79.208 86.837,79.208 84.9,81.145 84.9,93.884 85.08,94.064 100.32,94.064 100.5,93.884 100.5,79.3 98.896,77.696

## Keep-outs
Keep-Out Layer:
  lines w0.1: 0,9.5 4,9.5 cw(c4,4) 9.5,4 9.5,0 ; 0,54.5 4,54.5 ccw(c4,60) 4,65.5 0,65.5 ; 0,90.5 4,90.5 ccw(c4,96) 9.5,96 9.5,100 ; 100.5,0 100.5,4 cw(c106,4) 106,9.5 110,9.5 ; 100.5,100 100.5,96 ccw(c106,96) 106,90.5 110,90.5 ; 110,54.5 106,54.5 cw(c106,60) 106,65.5 110,65.5

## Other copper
Top Layer:
  pour cut-out: 110,77.688 67.726,77.688 61.374,84.04 39.555,84.04 39.515,84 39.515,99.991 39.524,100 31.33,100 31.33,80.17 34.1,77.4 56.7,77.4 64.388,69.712 110,69.712
  pour cut-out: 45.293,64.841 45.631,64.504 46.304,63.83 46.304,62.467 46.719,62.052 49.748,62.052 49.916,61.884 49.916,55.38 50.063,55.233 50.966,55.233 51.112,55.379 51.112,61.881 51.251,62.021 53.909,62.021 54.448,62.559 54.448,64.189 54.862,64.603 55.165,64.905 55.165,69.495 54.048,70.612 46.522,70.612 45.293,69.383
  text ".Layer_Name" at 18.948,-21.59 h1.52
Ground Layer:
  pour cut-out: 110,77.688 67.726,77.688 61.374,84.04 39.555,84.04 39.515,84 39.515,99.991 39.524,100 31.33,100 31.33,80.17 34.1,77.4 56.7,77.4 64.388,69.712 110,69.712
  region net GND: 49.708,55.457 49.708,55.431 49.995,55.144 49.716,54.864 49.29,54.864 49.264,54.89 49.264,55.233 49.264,56.114 49.4,56.25 49.528,56.25 49.708,56.07 49.708,55.846
  region net Gnd1: 50.063,56.21 50.063,55.423 50.121,55.365 50.915,55.365 50.95,55.4 50.95,56.21
  text ".Layer_Name" at 21.742,-22.248 h1.52
Power Layer:
  pour cut-out: 110,77.688 67.726,77.688 61.374,84.04 39.555,84.04 39.515,84 39.515,99.991 39.524,100 31.33,100 31.33,80.17 34.1,77.4 56.7,77.4 64.388,69.712 110,69.712
  pour cut-out: 45.293,64.841 45.631,64.504 46.304,63.83 46.304,62.467 46.719,62.052 49.748,62.052 49.916,61.884 49.916,55.38 50.063,55.233 50.966,55.233 51.112,55.379 51.112,61.881 51.251,62.021 53.909,62.021 54.448,62.559 54.448,64.189 54.862,64.603 55.165,64.905 55.165,69.495 54.048,70.612 46.522,70.612 45.293,69.383
  text ".Layer_Name" at 18.817,-22.502 h1.52
Bottom Layer:
  pour cut-out: 110,77.688 67.726,77.688 61.374,84.04 39.555,84.04 39.515,84 39.515,99.991 39.524,100 31.33,100 31.33,80.17 34.1,77.4 56.7,77.4 64.388,69.712 110,69.712
  pour cut-out: 45.293,64.841 45.631,64.504 46.304,63.83 46.304,62.467 46.719,62.052 49.748,62.052 49.916,61.884 49.916,55.38 50.063,55.233 50.966,55.233 51.112,55.379 51.112,61.881 51.251,62.021 53.909,62.021 54.448,62.559 54.448,64.189 54.862,64.603 55.165,64.905 55.165,69.495 54.048,70.612 46.522,70.612 45.293,69.383
  text ".Layer_Name" at 20.599,-21.488 h1.52
Multi-Layer:
  pour cut-out: 9.5,0 9.5,6.025 20.549,6.025 20.549,0
  pour cut-out: 45.1,82.85 45.1,85.5 48.015,85.5 48.015,82.85

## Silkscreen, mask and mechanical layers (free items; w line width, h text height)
Top Overlay:
  drawing of 59 lines, arcs and shapes, not listed
  text "TX" at 69.632,96.896 h1.2 r90
  text "RX" at 72.172,96.896 h1.2 r90
  text "TX" at 94.872,96.896 h1.2 r90
  text "RX" at 97.412,96.896 h1.2 r90
  text "GND" at 62.012,95.397 h1.2 r90
  text "VDD" at 67.092,95.397 h1.2 r90
  text "GND" at 87.252,95.397 h1.2 r90
  text "VDD" at 92.332,95.397 h1.2 r90
  text "GND" at 12.421,92.939 h0.76
  text "I" at 107.347,86.621 h7.62 r90
  text "GND" at 0.7,85.62 h1
  text "RST" at 0.7,83.08 h1
  text "SWCLK" at 0.7,80.54 h1
  text "G" at 108.294,78.84 h10.16 r90
  text "SWDIO" at 0.7,78 h1
  text "+3V3" at 0.7,75.46 h1
  text "GND" at 34.1,69.135 h0.76
  text "J" at 100.374,40.51 h15.24 r90
  text "+3V3" at 0.7,36.89 h1
  text "WARNING!" at 26.163,34.359 h2
  text "+5V" at 0.7,34.35 h1
  text "STEVAL-KiTXCBC / STEVAL$KiTXCBCA" at 107.576,33.5 h2.6 r90
  text "HIGH VOLTAGE" at 24.815,32.673 h1.8
  text "GPIO7" at 0.7,31.81 h1
  text "ON BOARD" at 26.535,31.173 h1.8
  text "GPIO6" at 0.7,29.27 h1
  text "GPIO5" at 0.7,26.73 h1
  text "GND" at 109.466,24.649 h0.76 r90
  text "GPIO4" at 0.7,24.19 h1
  text "GND" at 29.9,24.084 h0.76
  text "GPIO3" at 0.7,21.65 h1
  text "GPIO2" at 0.7,19.11 h1
  text "+5V" at 26.552,17.712 h0.76
  text "NC" at 0.7,16.57 h1
  text "GND" at 74.063,14.379 h0.76
  text "GND" at 0.7,14.03 h1
  text "+3V3" at 22.995,14.023 h0.76
  text "UDC" at 66.9,11.8 h0.64 r90
  text "IDCp" at 68.9,11.7 h0.64 r90
  text "Heatsink / temp_p" at 63.2,10.1 h0.64 r90
  text "TempSens2" at 61.2,10.058 h0.64 r90
  text "GND" at 38.581,7.761 h0.76
  text "PWM_1H" at 48.21,7.761 h0.64 r90
  text "PWM_1L*" at 49.271,7.761 h0.64 r90
  text "GND" at 56.891,7.761 h0.76 r90
  text "IACp" at 69.718,7.761 h0.64 r90
  text "GND" at 72.131,7.761 h0.76 r90
  text "GND" at 74.671,7.761 h0.76 r90
  text "Zero-X" at 54.762,7.62 h0.76 r90
  text "pwm_en/SD*" at 50.444,7.53 h0.64 r90
  text "1" at 34.011,6.502 h0.64
  text "31" at 75.832,6.297 h0.64
  text "Cook." at 9.617,5.7 h1
  text "Conc." at 15.517,5.7 h1
  text "2" at 33.884,3.759 h0.64
  text "32" at 75.731,3.757 h0.64
  text "P1" at 33.5,1.5 h0.64
  text "FOR EVALUATION ONLY / NOT FCC APPROVED / FOR RESALE" at 78.75,1.25 h2
  text "+24V" at 36.378,0.284 h0.64 r90
  text "+16V" at 39.144,0.284 h0.64 r90
  text "+5V" at 41.682,0.284 h0.64 r90
  text "+3V3" at 44.222,0.284 h0.64 r90
  text "Fan1 / PWM" at 47.246,0.284 h0.64 r90
  text "Fan2 / PWM" at 49.786,0.284 h0.64 r90
  text "LINE / en" at 52.245,0.284 h0.64 r90
  text "16V / en" at 54.736,0.284 h0.76 r90
  text "GND" at 56.863,0.284 h0.76 r90
  text "Temp / sen3" at 59.977,0.284 h0.64 r90
  text "Ucap" at 62.098,0.284 h0.64 r90
  text "Ubri / dge" at 65.112,0.284 h0.64 r90
  text "IDCn" at 67.178,0.284 h0.64 r90
  text "IACn" at 69.718,0.284 h0.64 r90
  text "GND" at 72.258,0.284 h0.76 r90
  text "GND" at 74.798,0.284 h0.76 r90
  text ".Layer_Name" at 20.599,-20.937 h1.52
Bottom Overlay:
  lines w0.152: 36.04,8.328 36.04,8.839 38.583,8.839 ; 41.25,8.839 43.66,8.839 43.66,8.328 ; 59.182,8.23 59.182,8.534
  text "Temp_p" at 60.681,9.576 h0.64 r270
  text "GND" at 41.121,8.328 h0.76
  text "GND" at 71.145,8.28 h0.76 r270
  text "GND" at 73.685,8.28 h0.76 r270
  text "pwm_en/SD*" at 50.444,8.204 h0.64 r270
  text "Heatsink" at 61.747,8.153 h0.64 r270
  text "IDCp" at 65.916,8.15 h0.64 r270
  text "PWM_1H" at 46.05,8.128 h0.64 r270
  text "PWM_1L*" at 48.472,8.125 h0.64 r270
  text "IACp" at 68.558,8.125 h0.64 r270
  text "Zero-X" at 53.21,8.111 h0.76 r270
  text "GND" at 55.75,8.111 h0.76 r270
  text "TempSens2" at 59.334,8.103 h0.64 r270
  text "UDC" at 63.384,7.232 h0.64 r270
  text "En" at 52.629,0.991 h0.76 r270
  text "en" at 50.114,0.711 h0.64 r270
  text "GND" at 55.748,0.561 h0.76 r270
  text "GND" at 73.553,0.561 h0.76 r270
  text "GND" at 71.039,0.535 h0.76 r270
  text "16V" at 53.563,0.484 h0.76 r270
  text "dge" at 62.611,0.406 h0.64 r270
  text "Ubri" at 63.678,0.406 h0.64 r270
  text "PWM" at 47.644,0.276 h0.64 r270
  text "IDCn" at 66.193,0.276 h0.64 r270
  text "IACn" at 68.53,0.276 h0.64 r270
  text "PWM" at 44.95,0.251 h0.64 r270
  text "Fan2" at 48.459,0.256 h0.64 r270
  text "Sen3" at 57.76,0.254 h0.64 r270
  text "Temp" at 58.623,0.254 h0.64 r270
  text "Ucap" at 60.91,0.256 h0.64 r270
  text "+16V" at 38.072,0.23 h0.64 r270
  text "+5V" at 40.61,0.23 h0.64 r270
  text "+3V3" at 43.15,0.23 h0.64 r270
  text "Fan1" at 45.796,0.229 h0.64 r270
  text "+24V" at 35.306,0.127 h0.64 r270
  text "LINE" at 50.75,0.127 h0.64 r270
  text ".Layer_Name" at 21.26,-20.937 h1.52
Top Paste:
  text ".Layer_Name" at 21.006,-20.667 h1.52
Bottom Paste:
  text ".Layer_Name" at 20.752,-20.997 h1.52
Top Solder:
  text ".Layer_Name" at 20.498,-21.488 h1.52
Bottom Solder:
  text ".Layer_Name" at 21.107,-20.997 h1.52
M1 Board Outline:
  the board outline again, w0.254
  text ".Layer_Name" at 19.914,-21.073 h1.52
M2 Board Dimensions:
  text ".Layer_Name" at 19.583,-21.175 h1.52
M9 Title Sheet:
  text ".Layer_Name" at 19.863,-21.073 h1.52
M10 Fab Notes:
  text "FAB NOTES:" at 121.656,15.571 h1.27
  text "1) ALL CORE AND PREPREG THICKNESSES ARE UP TO FAB SHOP TO SELECT." at 128.562,12.029 h1.27
  text "2)ALL VIAS ARE  NON TENTED" at 128.562,9.305 h1.27
  text "3)VENDOR MAY ADJUST SOLDERMASK WHEREVER SOLDERMASK PADS ARE SAME SIZE(1:1)" at 128.562,6.784 h1.27
  text "AS PER MANUFACTURING CAPABILITIES AND ALL OTHER SOLDERMASK PADS SHALL NOT BE MODIFIED" at 131.043,3.914 h1.27
  text "PROVIDED NO ADJACENT COPPER IS EXPOSED AND NO CONFLICT PRODUCED WITH ANY STATED" at 131.043,1.348 h1.27
  text "\"VIA TENTING/COVERING\" REQUIREMENTS." at 131.043,-1.014 h1.27
  text "4)THIS IS NOT AN IMPEDANCE CONTROLLED BOARD" at 128.562,-4.011 h1.27
  text "5)BOARD THICKNESS IS 1.6MM +/- 10% TOLERANCE" at 128.562,-6.191 h1.27
  text "6)ALL FABRICATION ITEM MUST MEET OR EXCEED BEST INDUSTRY PRACTICE. IPC-A-600C (Commercial Std.)" at 128.562,-8.372 h1.27
  text "7)MINIMUM COPPER WALL THICKNESS OF PLATED-THRU   HOLES TO BE 0.001 INCH, WITH A MINIMUM ANNULAR RING OF 0.002 INCH" at 128.562,-10.552 h1.27
  text "8)MAX. WARP & TWIST TO BE .0075 INCHES PER INCH" at 128.562,-12.732 h1.27
  text "9)HOLE POSITIONAL TOLERANCE ACCURACY IS  +/- 3 MILS" at 128.562,-14.913 h1.27
  text "10)SOLDERMASK BOTH SIDES PER ARTWORK.GREEN LPI" at 128.562,-17.093 h1.27
  text "11)SILKSCREEN BOTH SIDES PER ARTWORK.COLOR=WHITE." at 128.562,-19.07 h1.27
  text ".Layer_Name" at 19.431,-20.971 h1.52
M11 Gerber Information:
  circle w0.254: c97.053,-28.213 r1.3
  region: 82.575,-29.306 71.819,-29.306 72.812,-26.813 80.67,-26.813 81.119,-26.054 83.327,-28.602
  region: 96.578,-20.977 81.051,-20.977 80.357,-22.752 79.146,-23.977 77.749,-22.117 77.749,-20.466 78.892,-19.069 80.328,-18.691 96.578,-18.691
  lines w0.254: 72.812,-26.813 81.604,-26.813 78.538,-23.276 cw(c80.342,-21.332) 80.582,-18.691 97.346,-18.691 96.584,-20.977 ; 76.126,-18.444 cw(c78.552,-19.414) 78.789,-16.812 ; 76.165,-18.411 71.819,-29.306 91.142,-29.306 ccw(c91.39,-26.572) 93.94,-27.592 ; 77.905,-22.346 83.327,-28.602 ; 78.159,-22.346 83.464,-28.467 ; 78.159,-22.092 83.464,-28.213 ; 78.257,-20.977 91.25,-20.977 ; 78.286,-21.965 83.591,-28.086 ; 78.413,-21.838 83.718,-27.959 ; 78.54,-21.711 83.845,-27.832 ; 78.667,-21.584 83.972,-27.705 ; 78.722,-19.631 84.027,-25.753 ; 78.79,-16.812 98.24,-16.812 93.941,-27.589 ; 78.794,-21.457 84.045,-27.515 ; 78.794,-21.203 84.099,-27.324 ; 78.794,-20.949 84.099,-27.07 ; 78.794,-20.06 84.099,-26.181 ; 78.921,-20.822 84.226,-26.943 ; 78.921,-20.441 84.226,-26.562 ; 80.293,-26.827 ccw(c80.398,-26.292) 80.696,-25.834 ; 81.379,-20.963 ccw(c81.353,-21.531) 81.023,-21.993 83.388,-24.721 cw(c81.584,-26.665) 82.317,-29.214 ; 87.661,-29.102 90.55,-20.723 ; 87.883,-29.052 90.752,-20.731 ; 88.01,-29.052 90.879,-20.731 ; 88.264,-29.052 91.133,-20.731 ; 88.518,-29.052 91.387,-20.731 ; 88.772,-29.052 91.641,-20.731 ; 89.026,-29.052 91.895,-20.731 ; 89.28,-29.052 92.149,-20.731 ; 89.534,-29.052 92.403,-20.731 ; 89.788,-29.052 92.657,-20.731 ; 89.997,-29.102 92.886,-20.723 ; 92.886,-20.977 96.578,-20.977 ; 95.91,-20.974 96.672,-18.688 ; 96.076,-20.977 96.838,-18.691 ; 96.33,-20.977 97.092,-18.691
  lines w0.3: 10.049,-33.192 100.049,-33.192 100.049,-13.192 10.049,-13.192 ; 10.049,-28.192 70.049,-28.192 ; 10.049,-23.192 70.049,-23.192 ; 10.049,-18.192 70.049,-18.192 ; 10.049,-33.192 10.049,-13.192 ; 50.049,-33.192 50.049,-18.192 ; 70.049,-33.192 70.049,-13.192 ; 87.661,-29.102 89.997,-29.102
  text "Project: MCU STAGE BOARD" at 11.049,-16.408 h3
  text ".Layer_Name" at 19.279,-21.073 h1.52
  text "Layer:" at 11.049,-21.492 h3
  text "Variant: '.VariantName'" at 11.049,-26.492 h3
  text "R" at 96.545,-28.975 h1.52
  text "YEAR: 2022" at 11.049,-31.492 h3
  text "Rev: A" at 51.108,-31.492 h3
M12 Stackup:
  drawing of 307 lines, arcs and shapes, not listed
  text "Layer" at 122.517,111.521 h1.52
  text "Name" at 132.929,111.521 h1.52
  text "Material" at 156.544,111.521 h1.52
  text "Thickness" at 178.382,111.521 h1.52
  text "Constant" at 194.888,111.521 h1.52
  text "Board Layer Stack" at 209.363,111.521 h1.52
  text "Top Overlay" at 132.929,108.473 h1.52
  text "Top Solder" at 132.929,105.425 h1.52
  text "Solder Resist" at 156.544,105.425 h1.52
  text "0.50mil" at 178.382,105.425 h1.52
  text "3.5" at 194.888,105.425 h1.52
  text "1" at 122.517,102.377 h1.52
  text "Top Layer" at 132.929,102.377 h1.52
  text "1.40mil" at 178.382,102.377 h1.52
  text "1oz(35um)" at 244.973,102.388 h1.27
  text "Dielectric1" at 132.929,99.329 h1.52
  text "FR-4 High TG" at 156.544,99.329 h1.52
  text "14.17mil" at 178.382,99.329 h1.52
  text "4.2" at 194.888,99.329 h1.52
  text "2" at 122.517,96.281 h1.52
  text "Ground Layer" at 132.929,96.281 h1.52
  text "1.40mil" at 178.382,96.281 h1.52
  text "1oz(35um)" at 244.973,96.292 h1.27
  text "Dielectric 2" at 132.929,93.233 h1.52
  text "FR-4 High TG" at 156.544,93.233 h1.52
  text "27.95mil" at 178.382,93.233 h1.52
  text "4.2" at 194.888,93.233 h1.52
  text "3" at 122.517,90.185 h1.52
  text "Power Layer" at 132.929,90.185 h1.52
  text "1.40mil" at 178.382,90.185 h1.52
  text "1oz(35um)" at 244.973,90.196 h1.27
  text "Dielectric 3" at 132.929,87.137 h1.52
  text "FR-4 High TG" at 156.544,87.137 h1.52
  text "14.17mil" at 178.382,87.137 h1.52
  text "4.2" at 194.888,87.137 h1.52
  text "4" at 122.517,84.089 h1.52
  text "Bottom Layer" at 132.929,84.089 h1.52
  text "1.40mil" at 178.382,84.089 h1.52
  text "1oz(35um)" at 244.973,83.555 h1.27
  text "Bottom Solder" at 132.929,81.041 h1.52
  text "Solder Resist" at 156.544,81.041 h1.52
  text "0.50mil" at 178.382,81.041 h1.52
  text "3.5" at 194.888,81.041 h1.52
  text "Bottom Overlay" at 132.929,77.993 h1.52
  text "COPPER THICKNESS: FINISHED" at 120.818,75.083 h1.27
  text ".Layer_Name" at 19.329,-20.87 h1.52
Drill Drawing:
  drawing of 218 lines, arcs and shapes, not listed
  text "PCB SPECIFICATIONS :" at 0.924,151.016 h3
  text "A.   MATERIAL :" at 0.924,147.016 h3
  text "FR-4 HIGH TG" at 39.424,147.016 h3
  text "B.   MATERIAL FAMILY :" at 0.924,144.016 h3
  text "N/A" at 39.424,144.016 h3
  text "x   GREEN" at 39.624,141.249 h3
  text "WHITE" at 59.352,141.068 h3
  text "C.   SOLDERMASK COLOR :" at 0.924,141.016 h3
  text "BLUE" at 74.174,141.016 h3
  text "BLACK" at 90.174,141.016 h3
  text "D.   SILKSCREEN COLOR :" at 0.924,138.016 h3
  text "X  WHITE" at 39.424,138.016 h3
  text "YELLOW" at 55.924,138.016 h3
  text "BLACK" at 74.174,138.016 h3
  text "Blue ink PANTONE 2955" at 90.174,138.016 h3
  text "E.   SURFACE FINISH :" at 0.924,135.016 h3
  text "X  ENIG" at 39.424,135.016 h3
  text "IMMERSION SILVER" at 55.924,135.016 h3
  text "IMMERSION TIN" at 90.174,135.016 h3
  text "HASL" at 39.424,132.016 h3
  text "HASL (PB-FREE)" at 55.924,132.016 h3
  text "GOLDEN FINGER" at 90.174,132.016 h3
  text "MINIMUM PARAMETERS" at 148.41,131.573 h3
  text "F.   IMPEDANCE CONTROL :" at 0.924,129.016 h3
  text "X  NO" at 39.424,129.016 h3
  text "YES  (SEE IMPEDANCE TABLE FOR DETAIL INFORMATION)" at 55.924,129.016 h3
  text "DEFAULT" at 148.41,126.073 h3
  text "G.   VIA TENTING :" at 0.924,126.016 h3
  text "YES" at 58.928,125.781 h3
  text "X  NO" at 39.525,125.638 h3
  text "TRACKS : 0.152mm           / GAPS      : 0.15mm" at 148.41,120.323 h3
  text "H.   STACK-UP :" at 0.924,120.016 h3
  text "SEE LAYER STACK-UP SEQUENCE FOR OVERALL THICKNESS." at 39.424,120.016 h3
  text "Symbol" at 122.588,82.002 h1.83
  text "Count" at 135.437,82.002 h1.83
  text "Hole Size" at 150.673,82.002 h1.83
  text "Plated" at 179.874,82.002 h1.83
  text "Via/Pad" at 192.723,82.002 h1.83
  text "57" at 135.437,78.192 h1.52
  text "0.300mm (11.81mil)" at 150.673,78.192 h1.52
  text "PTH" at 179.874,78.192 h1.52
  text "Via" at 192.723,78.192 h1.52
  text "249" at 135.437,74.382 h1.52
  text "0.305mm (12.00mil)" at 150.673,74.382 h1.52
  text "PTH" at 179.874,74.382 h1.52
  text "Via" at 192.723,74.382 h1.52
  text "9" at 135.437,70.572 h1.52
  text "0.310mm (12.21mil)" at 150.673,70.572 h1.52
  text "PTH" at 179.874,70.572 h1.52
  text "Via" at 192.723,70.572 h1.52
  text "36" at 135.437,66.762 h1.52
  text "0.400mm (15.75mil)" at 150.673,66.762 h1.52
  text "PTH" at 179.874,66.762 h1.52
  text "Pad" at 192.723,66.762 h1.52
  text "14" at 135.437,62.952 h1.52
  text "0.700mm (27.56mil)" at 150.673,62.952 h1.52
  text "PTH" at 179.874,62.952 h1.52
  text "Pad" at 192.723,62.952 h1.52
  text "3" at 135.437,59.142 h1.52
  text "0.800mm (31.50mil)" at 150.673,59.142 h1.52
  text "PTH" at 179.874,59.142 h1.52
  text "Pad" at 192.723,59.142 h1.52
  text "48" at 135.437,55.332 h1.52
  text "0.900mm (35.43mil)" at 150.673,55.332 h1.52
  text "PTH" at 179.874,55.332 h1.52
  text "Pad" at 192.723,55.332 h1.52
  text "2" at 135.437,51.522 h1.52
  text "0.914mm (36.00mil)" at 150.673,51.522 h1.52
  text "PTH" at 179.874,51.522 h1.52
  text "Pad" at 192.723,51.522 h1.52
  text "37" at 135.437,47.712 h1.52
  text "1.000mm (39.37mil)" at 150.673,47.712 h1.52
  text "PTH" at 179.874,47.712 h1.52
  text "Pad" at 192.723,47.712 h1.52
  text "4" at 135.437,43.902 h1.52
  text "1.200mm (47.24mil)" at 150.673,43.902 h1.52
  text "PTH" at 179.874,43.902 h1.52
  text "Pad" at 192.723,43.902 h1.52
  text "7" at 135.437,40.092 h1.52
  text "1.300mm (51.18mil)" at 150.673,40.092 h1.52
  text "PTH" at 179.874,40.092 h1.52
  text "Pad" at 192.723,40.092 h1.52
  text "4" at 135.437,36.282 h1.52
  text "2.000mm (78.74mil)" at 150.673,36.282 h1.52
  text "NPTH" at 179.874,36.282 h1.52
  text "Pad" at 192.723,36.282 h1.52
  text "DRILL TOLERANCE:" at 211.246,33.197 h1.52
  text "6" at 135.437,32.472 h1.52
  text "3.200mm (125.98mil)" at 150.673,32.472 h1.52
  text "PTH" at 179.874,32.472 h1.52
  text "Pad" at 192.723,32.472 h1.52
  text "FOR 12MIL DRILL +0/-12MIL" at 211.324,29.901 h1.52
  text "476 Total" at 135.437,28.662 h1.52
  text "FOR PTH DRILL +/-3MIL" at 211.324,26.594 h1.52
  text "Slot definitions :" at 122.588,24.98 h1.52
  text "Routed Path Length" at 148.818,24.98 h1.52
  text "= Calculated from tool start centre position to tool end centre position." at 176.826,24.98 h1.52
  text "Hole Length" at 148.818,22.441 h1.52
  text "= Routed Path Length + Tool Size = Slot length as defined in the PCB layout" at 166.415,22.441 h1.52
  text ".Layer_Name" at 20.523,-21.09 h1.52

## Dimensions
1.5,0 to 1.5,100 on M2 Board Dimensions
110,1.5 to 0,1.5 on M2 Board Dimensions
